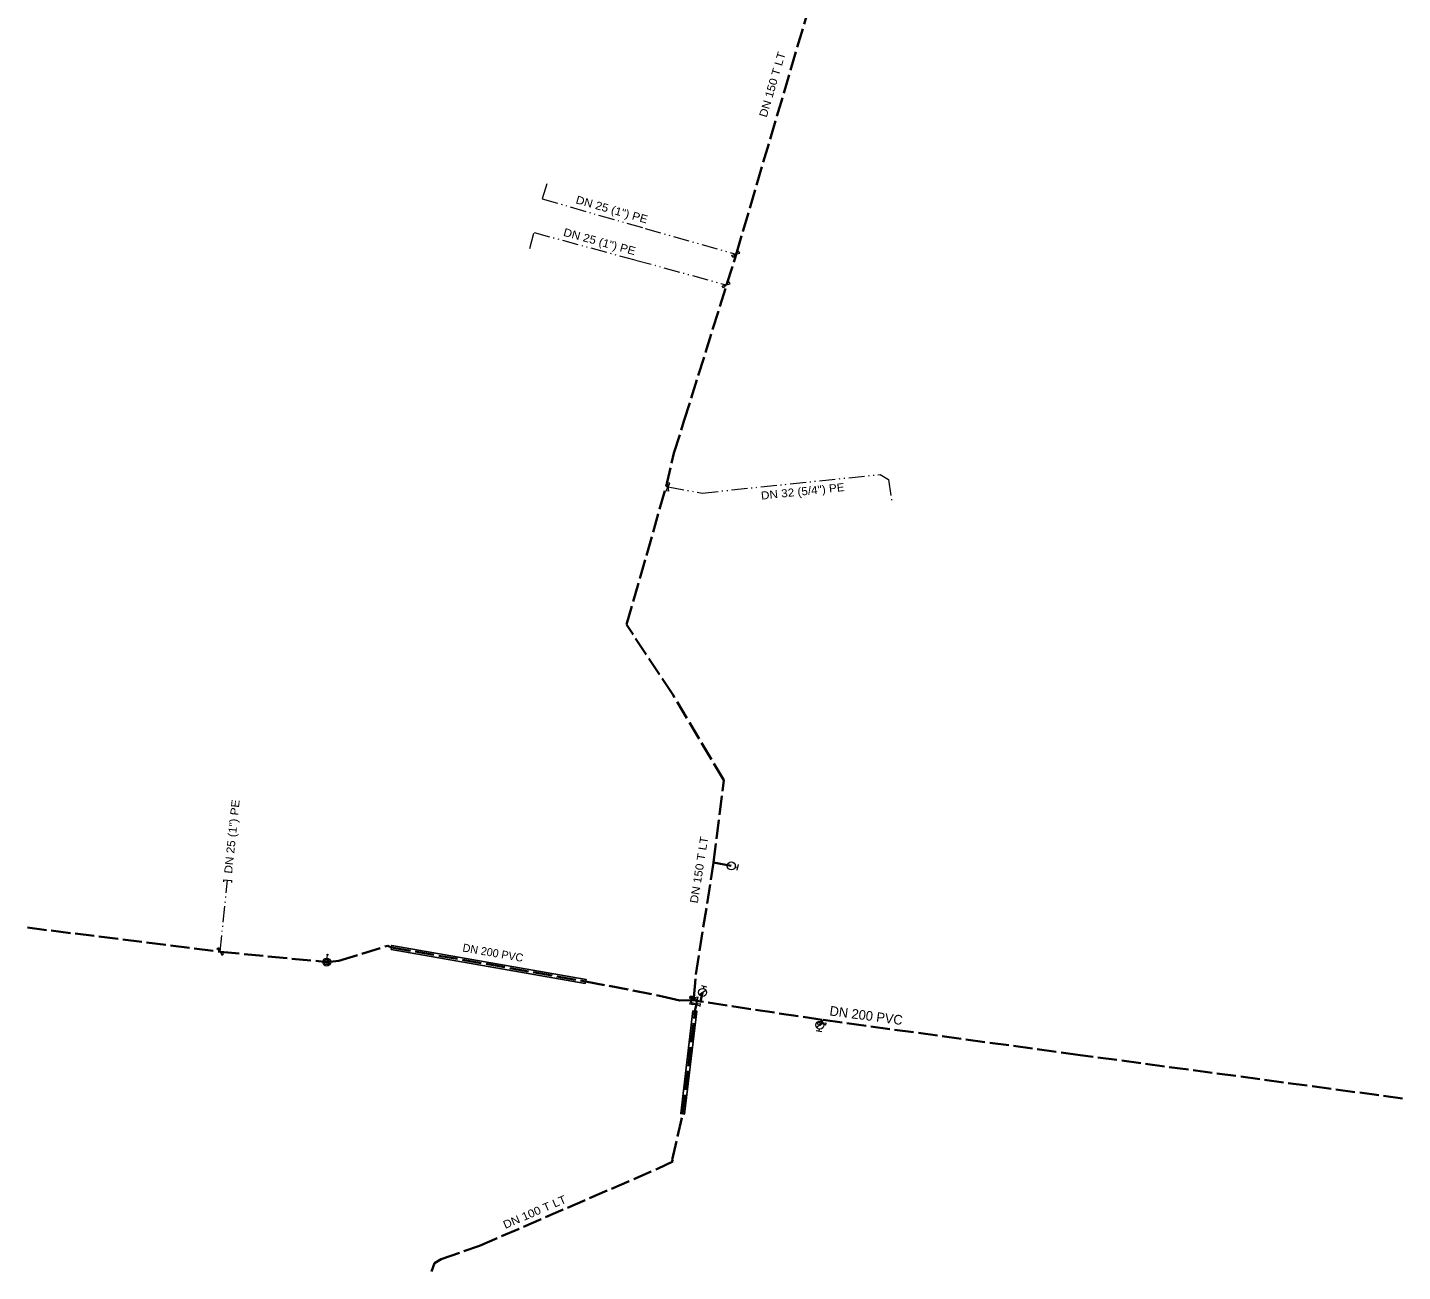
# Model space of a CAD drawing. Extents: x -645287 to -645115, y -1043737 to -1043439.
# Drawn here: x -645287.2 to -645115.4, y -1043736.6 to -1043581.1 of the extents above; entities that cross this region are included whole.
import ezdxf
from ezdxf.enums import TextEntityAlignment as Align

# ---------------------------------------------------------------- set-up
doc = ezdxf.new("R2010")
doc.units = 0
doc.header["$LTSCALE"] = 0.4
doc.linetypes.add('DASH_DOUBLE_DOT', pattern=[9.2, 5, -1.2, 0.3, -1.2, 0.3, -1.2])
doc.linetypes.add('LONG_DASHED', pattern=[7.5, 6, -1.5])
for name, color, linetype, lineweight in [('10', 7, 'Continuous', 13), ('21', 7, 'LONG_DASHED', 35), ('32', 7, 'DASH_DOUBLE_DOT', 13), ('51', 7, 'Continuous', 25)]:
    doc.layers.add(name, color=color, linetype=linetype, lineweight=lineweight)
doc.layers.add('29', color=7, linetype='Continuous')
doc.layers.add('39', color=7, linetype='Continuous')

msp = doc.modelspace()

# ---------------------------------------------------------------- linework, layer by layer
at = {"layer": '10'}
for p, q in [((-645198.752, -1043685.998), (-645198.459, -1043686.062)), ((-645198.383, -1043685.72), (-645198.534, -1043686.404)), ((-645262.677, -1043687.614), (-645262.703, -1043687.863)), ((-645262.677, -1043687.614), (-645261.683, -1043687.718)), ((-645261.683, -1043687.718), (-645261.709, -1043687.967)), ((-645249.684, -1043696.906), (-645249.559, -1043697.061)), ((-645203.257, -1043701.952), (-645202.405, -1043701.429)), ((-645202.985, -1043700.831), (-645202.304, -1043700.993)), ((-645202.714, -1043701.204), (-645202.645, -1043700.912)), ((-645187.779, -1043705.47), (-645188.58, -1043706.069)), ((-645187.947, -1043706.612), (-645188.64, -1043706.512)), ((-645188.251, -1043706.265), (-645188.294, -1043706.562))]:
    msp.add_line(p, q, dxfattribs=at)
for points in [[(-645198.33, -1043609.075), (-645199.039, -1043609.842), (-645199.191, -1043609.584), (-645198.177, -1043609.334)], [(-645199.525, -1043612.888), (-645200.22, -1043613.668), (-645200.377, -1043613.412), (-645199.368, -1043613.143)], [(-645207.2, -1043638.016), (-645207.08, -1043639.053), (-645207.375, -1043639.001), (-645206.905, -1043638.069)], [(-645262.68, -1043696.866), (-645263.536, -1043696.268), (-645263.3, -1043696.082), (-645262.915, -1043697.052)], [(-645204.158, -1043703.168), (-645204.282, -1043702.131), (-645203.986, -1043702.183), (-645204.454, -1043703.116)], [(-645203.404, -1043702.302), (-645204.436, -1043702.458), (-645204.394, -1043702.161), (-645203.446, -1043702.599)], [(-645203.092, -1043703.122), (-645204.129, -1043703.238), (-645204.075, -1043702.943), (-645203.145, -1043703.417)], [(-645188.474, -1043705.668), (-645187.446, -1043705.492), (-645187.482, -1043705.789), (-645188.438, -1043705.371)]]:
    msp.add_lwpolyline(points, close=True, dxfattribs=at)
msp.add_lwpolyline([(-645249.737, -1043697.403), (-645249.684, -1043696.906), (-645249.839, -1043697.031)], dxfattribs=at)
for centre, radius in [((-645199.2399, -1043685.8903), 0.5), ((-645249.7898, -1043697.9005), 0.5), ((-645249.7898, -1043697.9005), 0.35), ((-645249.7898, -1043697.9005), 0.2), ((-645202.8301, -1043701.69), 0.5), ((-645188.1802, -1043705.7703), 0.5)]:
    msp.add_circle(centre, radius, dxfattribs=at)
at = {"layer": '21'}
for p, q in [((-645199.825, -1043613.291), (-645198.636, -1043609.473)), ((-645205.158, -1043630.32), (-645199.825, -1043613.291)), ((-645287.18, -1043693.602), (-645263.114, -1043696.617)), ((-645263.114, -1043696.617), (-645249.79, -1043697.9)), ((-645204.22, -1043702.65), (-645203.938, -1043702.673)), ((-645203.938, -1043702.673), (-645203.92, -1043702.38)), ((-645203.551, -1043702.734), (-645203.938, -1043702.673)), ((-645203.61, -1043703.18), (-645203.551, -1043702.734)), ((-645203.1, -1043702.824), (-645203.551, -1043702.734)), ((-645187.96, -1043705.58), (-645187.904, -1043705.121))]:
    msp.add_line(p, q, dxfattribs=at)
for points in [[(-645198.636, -1043609.473), (-645187.2, -1043570.69), (-645177.7, -1043538.91)], [(-645207.387, -1043638.491), (-645206.41, -1043634.32), (-645205.158, -1043630.32)], [(-645201.46, -1043685.48), (-645200.18, -1043675.16), (-645206.56, -1043664.47), (-645212.34, -1043655.73), (-645207.387, -1043638.491)], [(-645203.92, -1043702.38), (-645203.68, -1043699.46), (-645201.46, -1043685.48), (-645199.24, -1043685.89)], [(-645249.79, -1043697.9), (-645248.26, -1043697.76), (-645242.15, -1043695.86), (-645241.71, -1043696.07), (-645217.44, -1043700.32), (-645207.82, -1043702.19), (-645205.69, -1043702.71), (-645204.22, -1043702.65)], [(-645187.904, -1043705.121), (-645203.1, -1043702.824), (-645202.83, -1043701.69)], [(-645236.72, -1043736.57), (-645236.31, -1043735.52), (-645235.48, -1043735.04), (-645230.72, -1043733.36), (-645208.47, -1043723.75), (-645206.56, -1043722.83), (-645206.65, -1043722.62), (-645205.32, -1043716.86), (-645203.79, -1043704.01), (-645203.61, -1043703.18)], [(-645188.18, -1043705.77), (-645187.96, -1043705.58), (-645187.96, -1043705.58)], [(-645115.38, -1043714.94), (-645155.66, -1043709.52), (-645187.904, -1043705.121)]]:
    msp.add_lwpolyline(points, dxfattribs=at)
at = {"layer": '32'}
for p, q in [((-645210.015, -1043606.218), (-645198.684, -1043609.459)), ((-645211.205, -1043610.188), (-645199.873, -1043613.278)), ((-645198.684, -1043609.459), (-645198.636, -1043609.473)), ((-645199.873, -1043613.278), (-645199.825, -1043613.291)), ((-645207.387, -1043638.491), (-645207.14, -1043638.535)), ((-645263.108, -1043696.567), (-645262.18, -1043687.666)), ((-645263.114, -1043696.617), (-645263.108, -1043696.567))]:
    msp.add_line(p, q, dxfattribs=at)
for points in [[(-645222.311, -1043600.653), (-645222.894, -1043602.535), (-645210.015, -1043606.218)], [(-645224.407, -1043608.752), (-645223.878, -1043606.733), (-645211.205, -1043610.188)], [(-645207.14, -1043638.535), (-645202.876, -1043639.292), (-645202.876, -1043639.292)], [(-645202.876, -1043639.292), (-645180.645, -1043636.972), (-645179.606, -1043637.616), (-645179.208, -1043640.224)]]:
    msp.add_lwpolyline(points, dxfattribs=at)
at = {"layer": '51'}
for points in [[(-645241.753, -1043696.316), (-645217.483, -1043700.566), (-645217.397, -1043700.074), (-645241.667, -1043695.824)], [(-645204.038, -1043703.98), (-645205.568, -1043716.83), (-645205.072, -1043716.89), (-645203.542, -1043704.04)]]:
    msp.add_lwpolyline(points, close=True, dxfattribs=at)

# ---------------------------------------------------------------- texts
at = {"layer": '29', "width": 1.1}
for s, rotation, p in [('DN 150 T LT', 73.571, (-645193.6413, -1043588.3874)), ('DN 150 T LT', 80.977, (-645202.7791, -1043686.4574)), ('DN 100 T LT', 23.36, (-645223.6203, -1043729.5875))]:
    msp.add_text(s, height=1, rotation=rotation, dxfattribs=at).set_placement(p, align=Align.CENTER)
at = {"layer": '29'}
msp.add_text('DN 200 PVC', height=1, rotation=350.067, dxfattribs=at).set_placement((-645229.1042, -1043697.2268), align=Align.CENTER)
msp.add_text('DN 200 PVC', height=1.2, rotation=352.422, dxfattribs=at).set_placement((-645187.023, -1043704.562))
at = {"layer": '39', "width": 1.1}
for s, rotation, p in [('DN 25 (1") PE', 344.041, (-645214.3005, -1043604.3485)), ('DN 25 (1") PE', 344.75, (-645215.8345, -1043608.3523)), ('DN 32 (5/4") PE', 5.958, (-645190.2629, -1043639.5791)), ('DN 25 (1") PE', 84.05, (-645261.1426, -1043682.2798))]:
    msp.add_text(s, height=1, rotation=rotation, dxfattribs=at).set_placement(p, align=Align.CENTER)

doc.saveas('drawing.dxf')
